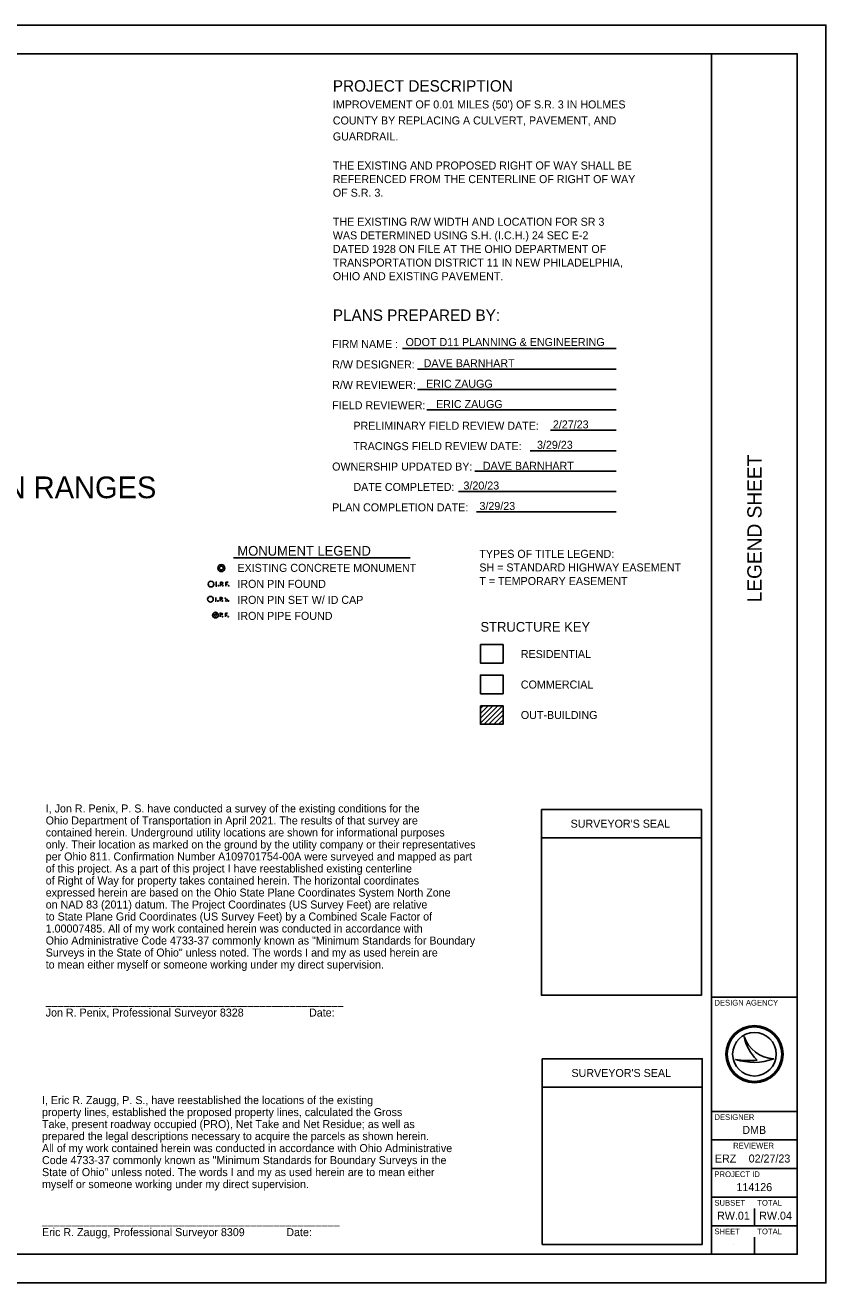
# Model space of a CAD drawing. Extents: x 0 to 34, y 0 to 22.
# Drawn here: x 19.98 to 34, y 0 to 22 of the extents above; entities that cross this region are included whole.
import ezdxf

# ---------------------------------------------------------------- set-up
doc = ezdxf.new("R2010")
doc.units = 0
for name, color, linetype in [('GM_X_Minor_Lake', 7, 'Continuous'), ('GM_X_Section', 7, 'Continuous'), ('SH_Border', 7, 'Continuous'), ('SH_Cut_Line', 7, 'Continuous'), ('SH_Data', 7, 'Continuous'), ('SH_Text', 7, 'Continuous')]:
    doc.layers.add(name, color=color, linetype=linetype)

msp = doc.modelspace()

# ---------------------------------------------------------------- linework, layer by layer
at = {"layer": 'GM_X_Section'}
msp.add_lwpolyline([(27.952, 10.305), (28.349, 10.305), (28.349, 10.631), (27.952, 10.631)], close=True, dxfattribs=at)
at = {"layer": 'SH_Border'}
for p, q in [((32, 0.5), (32, 21.5)), ((32, 5), (33.5, 5)), ((32, 3), (33.5, 3)), ((32, 2.5), (33.5, 2.5)), ((32, 2), (33.5, 2)), ((32, 1.5), (33.5, 1.5)), ((32, 1), (33.5, 1))]:
    msp.add_line(p, q, dxfattribs=at)
msp.add_lwpolyline([(1.5, 21.5), (33.5, 21.5), (33.5, 0.5), (1.5, 0.5)], close=True, dxfattribs=at)
at = {"layer": 'SH_Cut_Line'}
msp.add_lwpolyline([(0, 0), (34, 0), (34, 22), (0, 22)], close=True, dxfattribs=at)
at = {"layer": 'SH_Data'}
for p, q in [((29.021, 7.782), (31.821, 7.782)), ((32.567, 4.31), (32.567, 4.31)), ((32.75, 4), (32.75, 4)), ((32.417, 3.91), (32.417, 3.91)), ((33.087, 3.919), (33.087, 3.919)), ((29.036, 3.421), (31.836, 3.421)), ((32.75, 1), (32.75, 1.3)), ((32.375, 0.675), (32.375, 0.675)), ((32.75, 0.5), (32.75, 0.8))]:
    msp.add_line(p, q, dxfattribs=at)
for points in [[(29.021, 8.282), (31.821, 8.282), (31.821, 5.032), (29.021, 5.032)], [(29.036, 3.921), (31.836, 3.921), (31.836, 0.671), (29.036, 0.671)]]:
    msp.add_lwpolyline(points, close=True, dxfattribs=at)
for radius in [0.5, 0.477, 0.477, 0.382]:
    msp.add_circle((32.75, 4), radius, dxfattribs=at)
for centre, radius, start, end in [((33.116, 4.498), 0.58, 198.9257, 198.9319), ((33.347, 4.47), 0.796, 191.6379, 191.6421), ((33.116, 4.498), 0.58, 198.9319, 267.1657), ((33.347, 4.47), 0.796, 191.6421, 226.0947), ((32.739, 4.87), 1.013, 251.4576, 290.0832), ((32.648, 5.154), 1.266, 259.4964, 259.4995), ((32.739, 4.87), 1.013, 251.4527, 251.4576), ((32.648, 5.154), 1.266, 259.4995, 276.6672)]:
    msp.add_arc(centre, radius, start, end, dxfattribs=at)
at = {"layer": 'SH_Text'}
for p, q in [((26.59, 16.342), (30.327, 16.342)), ((26.854, 15.985), (30.327, 15.985)), ((26.854, 15.628), (30.327, 15.628)), ((27.018, 15.271), (30.327, 15.271)), ((29.181, 14.913), (30.327, 14.913)), ((28.824, 14.556), (30.327, 14.556)), ((27.854, 14.199), (30.327, 14.199)), ((27.569, 13.842), (30.327, 13.842)), ((27.884, 13.485), (30.327, 13.485)), ((23.63, 12.682), (26.723, 12.682)), ((23.32, 12.256), (23.337, 12.256)), ((23.32, 12.256), (23.337, 12.256)), ((23.32, 12.189), (23.337, 12.189)), ((23.328, 12.189), (23.328, 12.256)), ((23.405, 12.224), (23.432, 12.224)), ((23.498, 12.189), (23.498, 12.256)), ((23.498, 12.256), (23.537, 12.256)), ((23.498, 12.224), (23.526, 12.224)), ((23.311, 11.924), (23.328, 11.924)), ((23.32, 11.924), (23.32, 11.99)), ((23.396, 11.958), (23.423, 11.958)), ((23.491, 11.967), (23.521, 11.951)), ((23.397, 11.683), (23.424, 11.683)), ((23.491, 11.648), (23.491, 11.715)), ((23.491, 11.715), (23.529, 11.715)), ((23.491, 11.682), (23.518, 11.682)), ((27.952, 10.094), (27.953, 10.096)), ((27.952, 10.044), (28.003, 10.096)), ((27.952, 9.959), (28.088, 10.096)), ((27.952, 9.875), (28.173, 10.096)), ((27.952, 9.79), (28.258, 10.096)), ((28.016, 9.77), (28.342, 10.096)), ((28.101, 9.77), (28.349, 10.018)), ((28.186, 9.77), (28.349, 9.933)), ((27.952, 9.774), (27.957, 9.77)), ((28.27, 9.77), (28.349, 9.848))]:
    msp.add_line(p, q, dxfattribs=at)
for points in [[(23.432, 12.256), (23.405, 12.256), (23.405, 12.189)], [(23.423, 11.99), (23.396, 11.99), (23.396, 11.924)], [(23.424, 11.715), (23.397, 11.715), (23.397, 11.648)]]:
    msp.add_lwpolyline(points, dxfattribs=at)
for points in [[(27.952, 11.166), (28.349, 11.166), (28.349, 10.84), (27.952, 10.84)], [(27.952, 10.096), (28.349, 10.096), (28.349, 9.77), (27.952, 9.77)]]:
    msp.add_lwpolyline(points, close=True, dxfattribs=at)
for centre, radius in [((23.418, 12.503), 0.0625), ((23.418, 12.503), 0.0333), ((23.237, 12.223), 0.05), ((23.368, 12.194), 0.00583), ((23.445, 12.194), 0.00583), ((23.547, 12.194), 0.00583), ((23.228, 11.957), 0.05), ((23.36, 11.928), 0.00583), ((23.436, 11.928), 0.00583), ((23.543, 11.928), 0.00583), ((23.314, 11.681), 0.05), ((23.314, 11.681), 0.0206), ((23.438, 11.653), 0.00583), ((23.539, 11.653), 0.00583)]:
    msp.add_circle(centre, radius, dxfattribs=at)
for centre, radius, start, end in [((23.429, 12.24), 0.0162, 278.8803, 81.1197), ((23.42, 11.974), 0.0162, 278.8803, 81.1197), ((23.497, 11.977), 0.0118, 126.2587, 236.3675), ((23.505, 11.952), 0.0276, 223.6695, 304.3963), ((23.511, 11.94), 0.0148, 311.4883, 47.9358), ((23.422, 11.699), 0.0162, 278.8803, 81.1197)]:
    msp.add_arc(centre, radius, start, end, dxfattribs=at)

# ---------------------------------------------------------------- texts
at = {"layer": 'GM_X_Minor_Lake'}
for s, p in [('THE EXISTING AND PROPOSED RIGHT OF WAY SHALL BE', (25.37, 19.475)), ('REFERENCED FROM THE CENTERLINE OF RIGHT OF WAY', (25.37, 19.237)), ('OF S.R. 3.', (25.37, 18.999)), ('THE EXISTING R/W WIDTH AND LOCATION FOR SR 3', (25.37, 18.491)), ('WAS DETERMINED USING S.H. (I.C.H.) 24 SEC E-2', (25.37, 18.253)), ('DATED 1928 ON FILE AT THE OHIO DEPARTMENT OF', (25.37, 18.015)), ('TRANSPORTATION DISTRICT 11 IN NEW PHILADELPHIA,', (25.37, 17.777)), ('OHIO AND EXISTING PAVEMENT.', (25.37, 17.539))]:
    msp.add_text(s, height=0.14, dxfattribs=at).set_placement(p)
at = {"layer": 'SH_Data'}
msp.add_text('LEGEND SHEET', height=0.25, rotation=90, dxfattribs=at).set_placement((32.875, 11.904))
for s, height, p in [('   CONGRESS LANDS NORTH OF OLD SEVEN RANGES  ', 0.38, (8.981, 13.725)), ("SURVEYOR'S SEAL", 0.14, (29.532, 7.962)), ('DESIGN AGENCY', 0.1, (32.05, 4.85)), ("SURVEYOR'S SEAL", 0.14, (29.547, 3.601)), ('DESIGNER', 0.1, (32.05, 2.85)), ('DMB', 0.14, (32.538, 2.605)), ('REVIEWER', 0.1, (32.378, 2.35)), ('ERZ', 0.14, (32.057, 2.105)), ('02/27/23', 0.14, (32.649, 2.105)), ('PROJECT ID', 0.1, (32.05, 1.85)), ('SUBSET', 0.1, (32.05, 1.35)), ('TOTAL', 0.1, (32.8, 1.35)), ('RW.01', 0.14, (32.096, 1.105)), ('RW.04', 0.14, (32.833, 1.105)), ('SHEET', 0.1, (32.05, 0.85)), ('TOTAL', 0.1, (32.8, 0.85))]:
    msp.add_text(s, height=height, dxfattribs=at).set_placement(p)
at = {"layer": 'SH_Text'}
for s, height, p in [('PROJECT DESCRIPTION', 0.2, (25.37, 20.837)), ("IMPROVEMENT OF 0.01 MILES (50') OF S.R. 3 IN HOLMES", 0.14, (25.37, 20.543)), ('COUNTY BY REPLACING A CULVERT, PAVEMENT, AND ', 0.14, (25.37, 20.263)), ('GUARDRAIL.', 0.14, (25.37, 19.983)), ('PLANS PREPARED BY:', 0.2, (25.37, 16.827)), ('ODOT D11 PLANNING & ENGINEERING', 0.14, (26.643, 16.387)), ('FIRM NAME :', 0.14, (25.358, 16.352)), ('R/W DESIGNER:', 0.14, (25.358, 15.995)), ('DAVE BARNHART', 0.14, (26.96, 16.017)), ('R/W REVIEWER:', 0.14, (25.358, 15.638)), ('ERIC ZAUGG', 0.14, (27.003, 15.657)), ('FIELD REVIEWER:', 0.14, (25.358, 15.281)), ('ERIC ZAUGG', 0.14, (27.177, 15.302)), ('PRELIMINARY FIELD REVIEW DATE:', 0.14, (25.73, 14.923)), ('2/27/23', 0.14, (29.222, 14.946)), ('TRACINGS FIELD REVIEW DATE:', 0.14, (25.73, 14.566)), ('3/29/23', 0.14, (28.944, 14.589)), ('OWNERSHIP UPDATED BY:', 0.14, (25.358, 14.209)), ('DAVE BARNHART', 0.14, (27.996, 14.222)), ('DATE COMPLETED:', 0.14, (25.73, 13.852)), ('3/20/23', 0.14, (27.657, 13.877)), ('3/29/23', 0.14, (27.937, 13.519)), ('PLAN COMPLETION DATE:', 0.14, (25.358, 13.495)), ('MONUMENT LEGEND', 0.17, (23.699, 12.72)), ('TYPES OF TITLE LEGEND:', 0.14, (27.934, 12.682)), ('EXISTING CONCRETE MONUMENT', 0.14, (23.699, 12.437)), ('SH = STANDARD HIGHWAY EASEMENT', 0.14, (27.934, 12.444)), ('T = TEMPORARY EASEMENT', 0.14, (27.934, 12.206)), ('IRON PIN FOUND', 0.14, (23.699, 12.157)), ('IRON PIN SET W/ ID CAP', 0.14, (23.699, 11.877)), ('IRON PIPE FOUND', 0.14, (23.699, 11.597)), ('STRUCTURE KEY', 0.17, (27.954, 11.39)), ('RESIDENTIAL', 0.14, (28.661, 10.93)), ('COMMERCIAL', 0.14, (28.661, 10.396)), ('OUT-BUILDING', 0.14, (28.661, 9.863)), ('I, Jon R. Penix, P. S. have conducted a survey of the existing conditions for the', 0.14, (20.344, 8.228)), ('Ohio Department of Transportation in April 2021. The results of that survey are', 0.14, (20.344, 8.018)), ('contained herein. Underground utility locations are shown for informational purposes', 0.14, (20.344, 7.808)), ('only. Their location as marked on the ground by the utility company or their representatives', 0.14, (20.344, 7.598)), ('per Ohio 811. Confirmation Number A109701754-00A were surveyed and mapped as part ', 0.14, (20.344, 7.388)), ('of this project. As a part of this project I have reestablished existing centerline', 0.14, (20.344, 7.178)), ('of Right of Way for property takes contained herein. The horizontal coordinates', 0.14, (20.344, 6.968)), ('expressed herein are based on the Ohio State Plane Coordinates System North Zone', 0.14, (20.344, 6.758)), ('on NAD 83 (2011) datum. The Project Coordinates (US Survey Feet) are relative', 0.14, (20.344, 6.548)), ('to State Plane Grid Coordinates (US Survey Feet) by a Combined Scale Factor of', 0.14, (20.344, 6.338)), ('1.00007485. All of my work contained herein was conducted in accordance with', 0.14, (20.344, 6.128)), ('Ohio Administrative Code 4733-37 commonly known as "Minimum Standards for Boundary', 0.14, (20.344, 5.918)), ('Surveys in the State of Ohio" unless noted. The words I and my as used herein are', 0.14, (20.344, 5.708)), ('to mean either myself or someone working under my direct supervision.', 0.14, (20.344, 5.498)), ('__________________________________________________                                        ', 0.14, (20.344, 4.868)), ('Jon R. Penix, Professional Surveyor 8328                      Date:                  ', 0.14, (20.344, 4.658)), ('I, Eric R. Zaugg, P. S., have reestablished the locations of the existing', 0.14, (20.279, 3.127)), ('property lines, established the proposed property lines, calculated the Gross', 0.14, (20.279, 2.917)), ('Take, present roadway occupied (PRO), Net Take and Net Residue; as well as', 0.14, (20.279, 2.707)), ('prepared the legal descriptions necessary to acquire the parcels as shown herein.', 0.14, (20.279, 2.497)), ('All of my work contained herein was conducted in accordance with Ohio Administrative', 0.14, (20.279, 2.287)), ('Code 4733-37 commonly known as "Minimum Standards for Boundary Surveys in the', 0.14, (20.279, 2.077)), ('State of Ohio" unless noted. The words I and my as used herein are to mean either', 0.14, (20.279, 1.867)), ('myself or someone working under my direct supervision.', 0.14, (20.279, 1.657)), ('114126', 0.14, (32.435, 1.605)), ('__________________________________________________                                        ', 0.14, (20.279, 1.027)), ('Eric R. Zaugg, Professional Surveyor 8309              Date:                  ', 0.14, (20.279, 0.817))]:
    msp.add_text(s, height=height, dxfattribs=at).set_placement(p)

doc.saveas('drawing.dxf')
